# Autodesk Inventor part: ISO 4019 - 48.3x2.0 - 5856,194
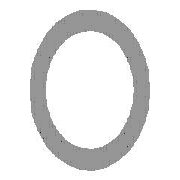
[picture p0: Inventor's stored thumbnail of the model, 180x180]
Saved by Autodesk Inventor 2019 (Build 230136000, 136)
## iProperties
IsCustomPart: 1
Created: 2018-01
Part Number: ISO 4019 - 48.3x2.0 - 5856,194
Material: Acier, doux
Description: Aciers de construction - Coupes creuses profilées formées à froid, soudées
Document SubType Name: Modeling
Standard: ISO
Designer: Fabian Perrée
Standard Revision: Second edition 2001-09-01
Standards Organization: ISO
Language: fr-FR
Size Designation: 48.3x2.0
Categories: <MemberInstance><Categories><Category DisplayName="Profilés" InternalName="089c4875-fa83-4c05-b084-43b9cc11f5ed" Mnemonic="GRDR"><CategoryParameter DisplayName=
Stock Number: 48.3x2.0
Density: 7.85 g/cm^3
Appearance: Semi-poli
Mass: 13373.5 g
Surface Area: 17042.2 cm^2
Volume: 1703.63 cm^3
_CCFamilyMember: 14
_CCFamilyDisplayName: ISO 4019 (Profils creux circulaires - Formés à froid) - Aciers de construction - Coupes creuses profilées formées à froid, soudées — ISO 4019 (Profils creux cir
_FrameMemberDoc: Frame Member File
_Version: 15.0.0
_GetPNFromCC: 1
G_W: 48,300 mm
G_H: 48,300 mm
G_L: 5856,194 mm
Author: Fabian Perrée
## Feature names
1. Corps
## Parameters: d0 = 48.3 mm, d1 = 2 mm, G_H = 48.3 mm, G_T = 2 mm, G_L = 5856.19449 mm, G_OFFSET_START = 0, G_OFFSET_END = 0, d4 = 0, d5 = 5856.19449 mm, B_L = 5856.19449 mm, d6 = 90 deg, d7 = 5856.19449 mm, MAS = 0.228 mm, d8 = 0, d9 = 0
